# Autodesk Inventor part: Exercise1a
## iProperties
Shininess: 64.0
Angle Display Precision: 2
Document Length Units: 11269
Document Angle Units: 11279
Document Time Units: 11290
Document Mass Units: 11283
Document Length Units Precision: 3
Document Angle Units Precision: 2
Created: 2002-03
Part Number: Exercise1a
Document SubType Name: Modeling
Density: 0.0
Volumn: 0.0
Area: 0.0
PropertySet Name: Model Information
Control State: 0
Master: False
Checked Out: False
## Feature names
1. Extrusion1
2. Extrusion2
3. Extrusion3
4. Extrusion4
